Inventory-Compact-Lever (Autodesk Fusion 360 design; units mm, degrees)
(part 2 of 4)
sketch "Spring-side loaded retained M4 nut" plane through (0, 0, 37.9) normal (0, 0, 1) x axis (1, 0, 0)
  line L1 (14.1362, -51.3) -> (16.2724, -55)
  line L2 (9.8638, -51.3) -> (14.1362, -51.3)
  line L3 (7.7276, -55) -> (9.8638, -51.3)
  line L4 (9.8638, -58.7) -> (7.7276, -55)
  line L5 (14.1362, -58.7) -> (9.8638, -58.7)
  line L6 (16.2724, -55) -> (14.1362, -58.7)
extrude "Extrude7" cut sketch "Spring-side loaded retained M4 nut" along normal blind 3.5
work_plane "WorkPlane8" AlongDistance 37.9 ExtraOffset 0
sketch "Spring cup guide bolts" plane through (0, 0, 37.9) normal (0, 0, 1) x axis (1, 0, 0)
  circle C1 centre (5, -55) radius 1.7
extrude "Extrude8" cut sketch "Spring cup guide bolts" along normal blind 14.2
work_plane "WorkPlane9" AlongDistance 37.9 ExtraOffset 0
sketch "Spring cup guide bolts (1)" plane through (0, 0, 37.9) normal (0, 0, 1) x axis (1, 0, 0)
  circle C1 centre (19, -55) radius 1.7
extrude "Extrude9" cut sketch "Spring cup guide bolts (1)" along normal blind 14.2
work_plane "WorkPlane11" AlongDistance -18 ExtraOffset 0
sketch "Dedicated thick stop lug" plane through (-18, 0, 0) normal (1, 0, 0) x axis (0, 0, -1)
  line L1 (-72, 5) -> (-72, -5)
  line L2 (-95, 5) -> (-72, 5)
  line L3 (-95, -5) -> (-95, 5)
  line L4 (-72, -5) -> (-95, -5)
extrude "Extrude11" add sketch "Dedicated thick stop lug" along normal blind 11.5
work_plane "WorkPlane12" AlongDistance -18 ExtraOffset 0
sketch "Rounded stop contact" plane through (-18, 0, 0) normal (1, 0, 0) x axis (0, 0, -1)
  circle C1 centre (-95, 0) radius 5
extrude "Extrude12" add sketch "Rounded stop contact" along normal blind 11.5
work_plane "WorkPlane10" AlongDistance -36 ExtraOffset 0
sketch "Broad stop support ear" plane through (-36, 0, 0) normal (1, 0, 0) x axis (0, 0, -1)
  line L1 (-60, -20) -> (-60, -44)
  line L2 (-90, -20) -> (-60, -20)
  line L3 (-90, -44) -> (-90, -20)
  line L4 (-60, -44) -> (-90, -44)
extrude "Extrude10" add sketch "Broad stop support ear" along normal blind 12
work_plane "WorkPlane11" AlongDistance -24 ExtraOffset 0
sketch "Integrated steel-core end stop" plane through (-24, 0, 0) normal (1, 0, 0) x axis (0, 0, -1)
  circle C1 centre (-79.6754, -33.9652) radius 6
extrude "Extrude11" add sketch "Integrated steel-core end stop" along normal blind 15
work_plane "WorkPlane12" AlongDistance -36.1 ExtraOffset 0
sketch "M5 stop reinforcement bolt" plane through (-36.1, 0, 0) normal (1, 0, 0) x axis (0, 0, -1)
  circle C1 centre (-79.6754, -33.9652) radius 2.7
extrude "Extrude12" cut sketch "M5 stop reinforcement bolt" along normal blind 27.2
work_plane "WorkPlane13" AlongDistance -15.4 ExtraOffset 0
sketch "M5 captive stop nut" plane through (-15.4, 0, 0) normal (1, 0, 0) x axis (0, 0, -1)
  line L1 (-83.8754, -31.5403) -> (-79.6754, -29.1154)
  line L2 (-83.8754, -36.39) -> (-83.8754, -31.5403)
  line L3 (-79.6754, -38.8149) -> (-83.8754, -36.39)
  line L4 (-75.4754, -36.39) -> (-79.6754, -38.8149)
  line L5 (-75.4754, -31.5403) -> (-75.4754, -36.39)
  line L6 (-79.6754, -29.1154) -> (-75.4754, -31.5403)
extrude "Extrude13" cut sketch "M5 captive stop nut" along normal blind 6.5
work_plane "WorkPlane14" AlongDistance -36 ExtraOffset 0
sketch "Broad stop support ear (1)" plane through (-36, 0, 0) normal (1, 0, 0) x axis (0, 0, -1)
  line L1 (-60, 44) -> (-60, 20)
  line L2 (-90, 44) -> (-60, 44)
  line L3 (-90, 20) -> (-90, 44)
  line L4 (-60, 20) -> (-90, 20)
extrude "Extrude14" add sketch "Broad stop support ear (1)" along normal blind 12
work_plane "WorkPlane15" AlongDistance -24 ExtraOffset 0
sketch "Integrated steel-core end stop (1)" plane through (-24, 0, 0) normal (1, 0, 0) x axis (0, 0, -1)
  circle C1 centre (-79.6754, 33.9652) radius 6
extrude "Extrude15" add sketch "Integrated steel-core end stop (1)" along normal blind 15
work_plane "WorkPlane16" AlongDistance -36.1 ExtraOffset 0
sketch "M5 stop reinforcement bolt (1)" plane through (-36.1, 0, 0) normal (1, 0, 0) x axis (0, 0, -1)
  circle C1 centre (-79.6754, 33.9652) radius 2.7
extrude "Extrude16" cut sketch "M5 stop reinforcement bolt (1)" along normal blind 27.2
work_plane "WorkPlane17" AlongDistance -15.4 ExtraOffset 0
sketch "M5 captive stop nut (1)" plane through (-15.4, 0, 0) normal (1, 0, 0) x axis (0, 0, -1)
  line L1 (-83.8754, 36.39) -> (-79.6754, 38.8149)
  line L2 (-83.8754, 31.5403) -> (-83.8754, 36.39)
  line L3 (-79.6754, 29.1154) -> (-83.8754, 31.5403)
  line L4 (-75.4754, 31.5403) -> (-79.6754, 29.1154)
  line L5 (-75.4754, 36.39) -> (-75.4754, 31.5403)
  line L6 (-79.6754, 38.8149) -> (-75.4754, 36.39)
extrude "Extrude17" cut sketch "M5 captive stop nut (1)" along normal blind 6.5
work_plane "WorkPlane13" AlongDistance -24 ExtraOffset 0
sketch "Restore shaft socket through stop-lug root" plane through (-24, 0, 0) normal (1, 0, 0) x axis (0, 0, -1)
  line L1 (-69.6247, 6.65) -> (-60.3753, 6.65)
  arc A1 centre (-65, 0) radius 8.1 clockwise from (-60.3753, 6.65) to (-69.6247, 6.65)
extrude "Extrude13" cut sketch "Restore shaft socket through stop-lug root" along normal blind 48
work_plane "WorkPlane10" AlongDistance -24.1 ExtraOffset 0
sketch "Cam sweep clearance through crossblock" plane through (-24.1, 0, 0) normal (1, 0, 0) x axis (0, 0, -1)
  circle C1 centre (-65, 0) radius 51
extrude "Extrude10" cut sketch "Cam sweep clearance through crossblock" along normal blind 48.2
work_plane "WorkPlane10" AlongDistance 36 ExtraOffset 0
sketch "Rigid sensor carriage support" plane through (36, 0, 0) normal (1, 0, 0) x axis (0, 0, -1)
  line L1 (-49, -18) -> (-49, -28)
  line L2 (-81, -18) -> (-49, -18)
  line L3 (-81, -28) -> (-81, -18)
  line L4 (-49, -28) -> (-81, -28)
extrude "Extrude10" add sketch "Rigid sensor carriage support" along normal blind 44
work_plane "WorkPlane11" AlongDistance -28.1 ExtraOffset 0
sketch "M3 sensor carriage heat set" plane through (0, -28.1, 0) normal (0, 1, 0) x axis (1, 0, 0)
  circle C1 centre (74, -65) radius 2
extrude "Extrude11" cut sketch "M3 sensor carriage heat set" along normal blind 6.8
work_plane "WorkPlane12" AlongDistance 36 ExtraOffset 0
sketch "Rigid sensor carriage support (1)" plane through (36, 0, 0) normal (1, 0, 0) x axis (0, 0, -1)
  line L1 (-49, 28) -> (-49, 18)
  line L2 (-81, 28) -> (-49, 28)
  line L3 (-81, 18) -> (-81, 28)
  line L4 (-49, 18) -> (-81, 18)
extrude "Extrude12" add sketch "Rigid sensor carriage support (1)" along normal blind 44
work_plane "WorkPlane13" AlongDistance 21.3 ExtraOffset 0
sketch "M3 sensor carriage heat set (1)" plane through (0, 21.3, 0) normal (0, 1, 0) x axis (1, 0, 0)
  circle C1 centre (74, -65) radius 2
extrude "Extrude13" cut sketch "M3 sensor carriage heat set (1)" along normal blind 6.8
work_plane "WorkPlane1" AlongDistance -24 ExtraOffset 0
sketch "Controlled follower end float" plane through (-24, 0, 0) normal (1, 0, 0) x axis (0, 0, -1)
  circle C1 centre (-12, -35) radius 6
extrude "Extrude1" new body sketch "Controlled follower end float" along normal blind 27.8 bodies "P21 Follower left axial spacer"
work_plane "WorkPlane2" AlongDistance -24.1 ExtraOffset 0
sketch "Pivot sleeve running clearance" plane through (-24.1, 0, 0) normal (1, 0, 0) x axis (0, 0, -1)
  circle C1 centre (-12, -35) radius 4.2
extrude "Extrude2" cut sketch "Pivot sleeve running clearance" along normal blind 28
work_plane "WorkPlane1" AlongDistance 20.2 ExtraOffset 0
sketch "Controlled follower end float" plane through (20.2, 0, 0) normal (1, 0, 0) x axis (0, 0, -1)
  circle C1 centre (-12, -35) radius 6
extrude "Extrude1" new body sketch "Controlled follower end float" along normal blind 3.8 bodies "P22 Follower right axial spacer"
work_plane "WorkPlane2" AlongDistance 20.1 ExtraOffset 0
sketch "Pivot sleeve running clearance" plane through (20.1, 0, 0) normal (1, 0, 0) x axis (0, 0, -1)
  circle C1 centre (-12, -35) radius 4.2
extrude "Extrude2" cut sketch "Pivot sleeve running clearance" along normal blind 4
work_plane "WorkPlane1" AlongDistance 3.1 ExtraOffset 0
sketch "Roller axle M3 nut" plane through (3.1, 0, 0) normal (1, 0, 0) x axis (0, 0, -1)
  line L1 (-14.75, 1.5877) -> (-12, 3.1754)
  line L2 (-14.75, -1.5877) -> (-14.75, 1.5877)
  line L3 (-12, -3.1754) -> (-14.75, -1.5877)
  line L4 (-9.25, -1.5877) -> (-12, -3.1754)
  line L5 (-9.25, 1.5877) -> (-9.25, -1.5877)
  line L6 (-12, 3.1754) -> (-9.25, 1.5877)
extrude "Extrude1" new body sketch "Roller axle M3 nut" along normal blind 2.4 bodies "HARDWARE Roller axle M3 nut"
work_plane "WorkPlane2" AlongDistance 3 ExtraOffset 0
sketch "Thread envelope" plane through (3, 0, 0) normal (1, 0, 0) x axis (0, 0, -1)
  circle C1 centre (-12, 0) radius 1.5
extrude "Extrude2" cut sketch "Thread envelope" along normal blind 2.6
work_plane "WorkPlane14" AlongDistance 23.9 ExtraOffset 0
sketch "Cam lateral service opening" plane through (23.9, 0, 0) normal (1, 0, 0) x axis (0, 0, -1)
  line L1 (-42.2047, 46.7373) -> (-43.8497, 47.5044)
  line L2 (-40.5875, 45.9133) -> (-42.2047, 46.7373)
  line L3 (-39, 45.0333) -> (-40.5875, 45.9133)
  line L4 (-37.4442, 44.0985) -> (-39, 45.0333)
  line L5 (-35.922, 43.11) -> (-37.4442, 44.0985)
  line L6 (-34.4352, 42.0689) -> (-35.922, 43.11)
  line L7 (-32.9856, 40.9766) -> (-34.4352, 42.0689)
  line L8 (-31.575, 39.8343) -> (-32.9856, 40.9766)
  line L9 (-30.2052, 38.6435) -> (-31.575, 39.8343)
  line L10 (-28.8778, 37.4057) -> (-30.2052, 38.6435)
  line L11 (-27.5943, 36.1222) -> (-28.8778, 37.4057)
  line L12 (-26.3565, 34.7948) -> (-27.5943, 36.1222)
  line L13 (-25.1657, 33.425) -> (-26.3565, 34.7948)
  line L14 (-24.0234, 32.0144) -> (-25.1657, 33.425)
  line L15 (-22.9311, 30.5648) -> (-24.0234, 32.0144)
  line L16 (-21.89, 29.078) -> (-22.9311, 30.5648)
  line L17 (-20.9015, 27.5558) -> (-21.89, 29.078)
  line L18 (-19.9667, 26) -> (-20.9015, 27.5558)
  line L19 (-19.0867, 24.4125) -> (-19.9667, 26)
  line L20 (-18.2627, 22.7953) -> (-19.0867, 24.4125)
  line L21 (-17.4956, 21.1503) -> (-18.2627, 22.7953)
  line L22 (-16.7864, 19.4795) -> (-17.4956, 21.1503)
  line L23 (-16.136, 17.785) -> (-16.7864, 19.4795)
  line L24 (-15.5451, 16.0689) -> (-16.136, 17.785)
  line L25 (-15.0144, 14.3331) -> (-15.5451, 16.0689)
  line L26 (-14.5446, 12.5799) -> (-15.0144, 14.3331)
  line L27 (-14.1363, 10.8114) -> (-14.5446, 12.5799)
  line L28 (-13.79, 9.0297) -> (-14.1363, 10.8114)
  line L29 (-13.5061, 7.237) -> (-13.79, 9.0297)
  line L30 (-13.2849, 5.4355) -> (-13.5061, 7.237)
  line L31 (-13.1267, 3.6273) -> (-13.2849, 5.4355)
  line L32 (-13.0317, 1.8148) -> (-13.1267, 3.6273)
  line L33 (-13, 0) -> (-13.0317, 1.8148)
  line L34 (-13.0317, -1.8148) -> (-13, 0)
  line L35 (-13.1267, -3.6273) -> (-13.0317, -1.8148)
  line L36 (-13.2849, -5.4355) -> (-13.1267, -3.6273)
  line L37 (-13.5061, -7.237) -> (-13.2849, -5.4355)
  line L38 (-13.79, -9.0297) -> (-13.5061, -7.237)
  line L39 (-14.1363, -10.8114) -> (-13.79, -9.0297)
  line L40 (-14.5446, -12.5799) -> (-14.1363, -10.8114)
  line L41 (-15.0144, -14.3331) -> (-14.5446, -12.5799)
  line L42 (-15.5451, -16.0689) -> (-15.0144, -14.3331)
  line L43 (-16.136, -17.785) -> (-15.5451, -16.0689)
  line L44 (-16.7864, -19.4795) -> (-16.136, -17.785)
  line L45 (-17.4956, -21.1503) -> (-16.7864, -19.4795)
  line L46 (-18.2627, -22.7953) -> (-17.4956, -21.1503)
  line L47 (-19.0867, -24.4125) -> (-18.2627, -22.7953)
  line L48 (-19.9667, -26) -> (-19.0867, -24.4125)
  line L49 (-20.9015, -27.5558) -> (-19.9667, -26)
  line L50 (-21.89, -29.078) -> (-20.9015, -27.5558)
  line L51 (-22.9311, -30.5648) -> (-21.89, -29.078)
  line L52 (-24.0234, -32.0144) -> (-22.9311, -30.5648)
  line L53 (-25.1657, -33.425) -> (-24.0234, -32.0144)
  line L54 (-26.3565, -34.7948) -> (-25.1657, -33.425)
  line L55 (-27.5943, -36.1222) -> (-26.3565, -34.7948)
  line L56 (-28.8778, -37.4057) -> (-27.5943, -36.1222)
  line L57 (-30.2052, -38.6435) -> (-28.8778, -37.4057)
  line L58 (-31.575, -39.8343) -> (-30.2052, -38.6435)
  line L59 (-32.9856, -40.9766) -> (-31.575, -39.8343)
  line L60 (-34.4352, -42.0689) -> (-32.9856, -40.9766)
  line L61 (-35.922, -43.11) -> (-34.4352, -42.0689)
  line L62 (-37.4442, -44.0985) -> (-35.922, -43.11)
  line L63 (-39, -45.0333) -> (-37.4442, -44.0985)
  line L64 (-40.5875, -45.9133) -> (-39, -45.0333)
  line L65 (-42.2047, -46.7373) -> (-40.5875, -45.9133)
  line L66 (-43.8497, -47.5044) -> (-42.2047, -46.7373)
  line L67 (-54.4248, -23.7522) -> (-43.8497, -47.5044)
  line L68 (-53.6024, -23.3686) -> (-54.4248, -23.7522)
  line L69 (-52.7937, -22.9566) -> (-53.6024, -23.3686)
  line L70 (-52, -22.5167) -> (-52.7937, -22.9566)
  line L71 (-51.2221, -22.0493) -> (-52, -22.5167)
  line L72 (-50.461, -21.555) -> (-51.2221, -22.0493)
  line L73 (-49.7176, -21.0344) -> (-50.461, -21.555)
  line L74 (-48.9928, -20.4883) -> (-49.7176, -21.0344)
  line L75 (-48.2875, -19.9172) -> (-48.9928, -20.4883)
  line L76 (-47.6026, -19.3218) -> (-48.2875, -19.9172)
  line L77 (-46.9389, -18.7028) -> (-47.6026, -19.3218)
  line L78 (-46.2972, -18.0611) -> (-46.9389, -18.7028)
  line L79 (-45.6782, -17.3974) -> (-46.2972, -18.0611)
  line L80 (-45.0828, -16.7125) -> (-45.6782, -17.3974)
  line L81 (-44.5117, -16.0072) -> (-45.0828, -16.7125)
  line L82 (-43.9656, -15.2824) -> (-44.5117, -16.0072)
  line L83 (-43.445, -14.539) -> (-43.9656, -15.2824)
  line L84 (-42.9507, -13.7779) -> (-43.445, -14.539)
  line L85 (-42.4833, -13) -> (-42.9507, -13.7779)
  line L86 (-42.0434, -12.2063) -> (-42.4833, -13)
  line L87 (-41.6314, -11.3976) -> (-42.0434, -12.2063)
  line L88 (-41.2478, -10.5752) -> (-41.6314, -11.3976)
  line L89 (-40.8932, -9.7398) -> (-41.2478, -10.5752)
  line L90 (-40.568, -8.8925) -> (-40.8932, -9.7398)
  line L91 (-40.2725, -8.0344) -> (-40.568, -8.8925)
  line L92 (-40.0072, -7.1666) -> (-40.2725, -8.0344)
  line L93 (-39.7723, -6.29) -> (-40.0072, -7.1666)
  line L94 (-39.5682, -5.4057) -> (-39.7723, -6.29)
  line L95 (-39.395, -4.5149) -> (-39.5682, -5.4057)
  line L96 (-39.253, -3.6185) -> (-39.395, -4.5149)
  line L97 (-39.1424, -2.7177) -> (-39.253, -3.6185)
  line L98 (-39.0633, -1.8137) -> (-39.1424, -2.7177)
  line L99 (-39.0158, -0.9074) -> (-39.0633, -1.8137)
  line L100 (-39, 0) -> (-39.0158, -0.9074)
  line L101 (-39.0158, 0.9074) -> (-39, 0)
  line L102 (-39.0633, 1.8137) -> (-39.0158, 0.9074)
  line L103 (-39.1424, 2.7177) -> (-39.0633, 1.8137)
  line L104 (-39.253, 3.6185) -> (-39.1424, 2.7177)
  line L105 (-39.395, 4.5149) -> (-39.253, 3.6185)
  line L106 (-39.5682, 5.4057) -> (-39.395, 4.5149)
  line L107 (-39.7723, 6.29) -> (-39.5682, 5.4057)
  line L108 (-40.0072, 7.1666) -> (-39.7723, 6.29)
  line L109 (-40.2725, 8.0344) -> (-40.0072, 7.1666)
  line L110 (-40.568, 8.8925) -> (-40.2725, 8.0344)
  line L111 (-40.8932, 9.7398) -> (-40.568, 8.8925)
  line L112 (-41.2478, 10.5752) -> (-40.8932, 9.7398)
  line L113 (-41.6314, 11.3976) -> (-41.2478, 10.5752)
  line L114 (-42.0434, 12.2063) -> (-41.6314, 11.3976)
  line L115 (-42.4833, 13) -> (-42.0434, 12.2063)
  line L116 (-42.9507, 13.7779) -> (-42.4833, 13)
  line L117 (-43.445, 14.539) -> (-42.9507, 13.7779)
  line L118 (-43.9656, 15.2824) -> (-43.445, 14.539)
  line L119 (-44.5117, 16.0072) -> (-43.9656, 15.2824)
  line L120 (-45.0828, 16.7125) -> (-44.5117, 16.0072)
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extrude "Extrude14" cut sketch "Cam lateral service opening" along normal blind 12.2
work_plane "WorkPlane15" AlongDistance 36 ExtraOffset 0
sketch "Clear service path beneath sensor rails" plane through (36, 0, 0) normal (1, 0, 0) x axis (0, 0, -1)
  line L1 (-48.9, -18) -> (-48.9, -28)
  line L2 (-56, -18) -> (-48.9, -18)
  line L3 (-56, -28) -> (-56, -18)
  line L4 (-48.9, -28) -> (-56, -28)
extrude "Extrude15" cut sketch "Clear service path beneath sensor rails" along normal blind 44.1
work_plane "WorkPlane16" AlongDistance 36 ExtraOffset 0
sketch "Clear service path beneath sensor rails (1)" plane through (36, 0, 0) normal (1, 0, 0) x axis (0, 0, -1)
  line L1 (-48.9, 28) -> (-48.9, 18)
  line L2 (-56, 28) -> (-48.9, 28)
  line L3 (-56, 18) -> (-56, 28)
  line L4 (-48.9, 18) -> (-56, 18)
extrude "Extrude16" cut sketch "Clear service path beneath sensor rails (1)" along normal blind 44.1
work_plane "WorkPlane11" AlongDistance -24 ExtraOffset 0
sketch "Raise mount clear of rail bolt axes" plane through (-24, 0, 0) normal (1, 0, 0) x axis (0, 0, -1)
  line L1 (-52, -44) -> (-52, -66)
  line L2 (-57, -44) -> (-52, -44)
  line L3 (-57, -66) -> (-57, -44)
  line L4 (-52, -66) -> (-57, -66)
extrude "Extrude11" add sketch "Raise mount clear of rail bolt axes" along normal blind 48
work_plane "WorkPlane12" AlongDistance -24 ExtraOffset 0
sketch "Close old block mounting hole" plane through (-24, 0, 0) normal (1, 0, 0) x axis (0, 0, -1)
  circle C1 centre (-44, -59) radius 2.01
extrude "Extrude12" add sketch "Close old block mounting hole" along normal blind 8.7
work_plane "WorkPlane13" AlongDistance -24.1 ExtraOffset 0
sketch "Raised M3 block insert" plane through (-24.1, 0, 0) normal (1, 0, 0) x axis (0, 0, -1)
  circle C1 centre (-52, -59) radius 2
extrude "Extrude13" cut sketch "Raised M3 block insert" along normal blind 8.9
work_plane "WorkPlane14" AlongDistance 15.3 ExtraOffset 0
sketch "Close old block mounting hole (1)" plane through (15.3, 0, 0) normal (1, 0, 0) x axis (0, 0, -1)
  circle C1 centre (-44, -59) radius 2.01
extrude "Extrude14" add sketch "Close old block mounting hole (1)" along normal blind 8.7
work_plane "WorkPlane15" AlongDistance 15.2 ExtraOffset 0
sketch "Raised M3 block insert (1)" plane through (15.2, 0, 0) normal (1, 0, 0) x axis (0, 0, -1)
  circle C1 centre (-52, -59) radius 2
extrude "Extrude15" cut sketch "Raised M3 block insert (1)" along normal blind 8.9
work_plane "WorkPlane18" AlongDistance -36 ExtraOffset 0
sketch "Close old plate mounting hole" plane through (-36, 0, 0) normal (1, 0, 0) x axis (0, 0, -1)
  circle C1 centre (-44, -59) radius 1.71
extrude "Extrude18" add sketch "Close old plate mounting hole" along normal blind 12
work_plane "WorkPlane19" AlongDistance -36.1 ExtraOffset 0
sketch "Raised M3 block fastener" plane through (-36.1, 0, 0) normal (1, 0, 0) x axis (0, 0, -1)
  circle C1 centre (-52, -59) radius 1.7
extrude "Extrude19" cut sketch "Raised M3 block fastener" along normal blind 12.2
work_plane "WorkPlane17" AlongDistance 24 ExtraOffset 0
sketch "Close old plate mounting hole" plane through (24, 0, 0) normal (1, 0, 0) x axis (0, 0, -1)
  circle C1 centre (-44, -59) radius 1.71
extrude "Extrude17" add sketch "Close old plate mounting hole" along normal blind 12
work_plane "WorkPlane18" AlongDistance 23.9 ExtraOffset 0
sketch "Raised M3 block fastener" plane through (23.9, 0, 0) normal (1, 0, 0) x axis (0, 0, -1)
  circle C1 centre (-52, -59) radius 1.7
extrude "Extrude18" cut sketch "Raised M3 block fastener" along normal blind 12.2
work_plane "WorkPlane16" AlongDistance -24 ExtraOffset 0
sketch "Close old block mounting hole (2)" plane through (-24, 0, 0) normal (1, 0, 0) x axis (0, 0, -1)
  circle C1 centre (-44, -51) radius 2.01
extrude "Extrude16" add sketch "Close old block mounting hole (2)" along normal blind 8.7
work_plane "WorkPlane17" AlongDistance -24.1 ExtraOffset 0
sketch "Raised M3 block insert (2)" plane through (-24.1, 0, 0) normal (1, 0, 0) x axis (0, 0, -1)
  circle C1 centre (-52, -51) radius 2
extrude "Extrude17" cut sketch "Raised M3 block insert (2)" along normal blind 8.9
work_plane "WorkPlane18" AlongDistance 15.3 ExtraOffset 0
sketch "Close old block mounting hole (3)" plane through (15.3, 0, 0) normal (1, 0, 0) x axis (0, 0, -1)
  circle C1 centre (-44, -51) radius 2.01
extrude "Extrude18" add sketch "Close old block mounting hole (3)" along normal blind 8.7
work_plane "WorkPlane19" AlongDistance 15.2 ExtraOffset 0
sketch "Raised M3 block insert (3)" plane through (15.2, 0, 0) normal (1, 0, 0) x axis (0, 0, -1)
  circle C1 centre (-52, -51) radius 2
extrude "Extrude19" cut sketch "Raised M3 block insert (3)" along normal blind 8.9
work_plane "WorkPlane20" AlongDistance -36 ExtraOffset 0
sketch "Close old plate mounting hole (1)" plane through (-36, 0, 0) normal (1, 0, 0) x axis (0, 0, -1)
  circle C1 centre (-44, -51) radius 1.71
extrude "Extrude20" add sketch "Close old plate mounting hole (1)" along normal blind 12
work_plane "WorkPlane21" AlongDistance -36.1 ExtraOffset 0
sketch "Raised M3 block fastener (1)" plane through (-36.1, 0, 0) normal (1, 0, 0) x axis (0, 0, -1)
  circle C1 centre (-52, -51) radius 1.7
extrude "Extrude21" cut sketch "Raised M3 block fastener (1)" along normal blind 12.2
work_plane "WorkPlane19" AlongDistance 24 ExtraOffset 0
sketch "Close old plate mounting hole (1)" plane through (24, 0, 0) normal (1, 0, 0) x axis (0, 0, -1)
  circle C1 centre (-44, -51) radius 1.71
extrude "Extrude19" add sketch "Close old plate mounting hole (1)" along normal blind 12
work_plane "WorkPlane20" AlongDistance 23.9 ExtraOffset 0
sketch "Raised M3 block fastener (1)" plane through (23.9, 0, 0) normal (1, 0, 0) x axis (0, 0, -1)
  circle C1 centre (-52, -51) radius 1.7
extrude "Extrude20" cut sketch "Raised M3 block fastener (1)" along normal blind 12.2
work_plane "WorkPlane20" AlongDistance 51.9 ExtraOffset 0
sketch "Continue adjuster bore" plane through (0, 0, 51.9) normal (0, 0, 1) x axis (1, 0, 0)
  circle C1 centre (12, -55) radius 2.2
extrude "Extrude20" cut sketch "Continue adjuster bore" along normal blind 5.2
work_plane "WorkPlane21" AlongDistance 51.9 ExtraOffset 0
sketch "Continue guide bore" plane through (0, 0, 51.9) normal (0, 0, 1) x axis (1, 0, 0)
  circle C1 centre (5, -55) radius 1.7
extrude "Extrude21" cut sketch "Continue guide bore" along normal blind 5.2
work_plane "WorkPlane22" AlongDistance 51.9 ExtraOffset 0
sketch "Continue guide bore (1)" plane through (0, 0, 51.9) normal (0, 0, 1) x axis (1, 0, 0)
  circle C1 centre (19, -55) radius 1.7
extrude "Extrude22" cut sketch "Continue guide bore (1)" along normal blind 5.2
work_plane "WorkPlane23" AlongDistance -24.1 ExtraOffset 0
sketch "Preserve cam sweep clearance" plane through (-24.1, 0, 0) normal (1, 0, 0) x axis (0, 0, -1)
  circle C1 centre (-65, 0) radius 51
extrude "Extrude23" cut sketch "Preserve cam sweep clearance" along normal blind 48.2
work_plane "WorkPlane8" AlongDistance 37.25 ExtraOffset 0
sketch "Flat shoulder aligns with shaft print bed" plane through (37.25, 0, 0) normal (1, 0, 0) x axis (0, 0, -1)
  line L1 (-54, 11) -> (-54, 6.5)
  line L2 (-76, 11) -> (-54, 11)
  line L3 (-76, 6.5) -> (-76, 11)
  line L4 (-54, 6.5) -> (-76, 6.5)
extrude "Extrude8" cut sketch "Flat shoulder aligns with shaft print bed" along normal blind 3.2
work_plane "WorkPlane1" AlongDistance -23.85 ExtraOffset 0
sketch "Controlled rotor axial clearance" plane through (-23.85, 0, 0) normal (1, 0, 0) x axis (0, 0, -1)
  circle C1 centre (-65, 0) radius 10
extrude "Extrude1" new body sketch "Controlled rotor axial clearance" along normal blind 16.85 bodies "P23 Left rotor thrust spacer"
work_plane "WorkPlane2" AlongDistance -23.95 ExtraOffset 0
sketch "Free spacer bore" plane through (-23.95, 0, 0) normal (1, 0, 0) x axis (0, 0, -1)
  circle C1 centre (-65, 0) radius 8.2
extrude "Extrude2" cut sketch "Free spacer bore" along normal blind 17.05
work_plane "WorkPlane1" AlongDistance 7 ExtraOffset 0
sketch "Controlled rotor axial clearance" plane through (7, 0, 0) normal (1, 0, 0) x axis (0, 0, -1)
  circle C1 centre (-65, 0) radius 10
extrude "Extrude1" new body sketch "Controlled rotor axial clearance" along normal blind 16.85 bodies "P24 Right rotor thrust spacer"
work_plane "WorkPlane2" AlongDistance 6.9 ExtraOffset 0
sketch "Free spacer bore" plane through (6.9, 0, 0) normal (1, 0, 0) x axis (0, 0, -1)
  circle C1 centre (-65, 0) radius 8.2
extrude "Extrude2" cut sketch "Free spacer bore" along normal blind 17.05
work_plane "WorkPlane22" AlongDistance -76 ExtraOffset 0
sketch "Restore rail bolt clearance after hole filling" plane through (0, -76, 0) normal (0, 1, 0) x axis (1, 0, 0)
  circle C1 centre (-30, -45) radius 2.7
extrude "Extrude22" cut sketch "Restore rail bolt clearance after hole filling" along normal blind 22
work_plane "WorkPlane23" AlongDistance 54 ExtraOffset 0
sketch "Restore rail bolt clearance after hole filling (1)" plane through (0, 54, 0) normal (0, 1, 0) x axis (1, 0, 0)
  circle C1 centre (-30, -45) radius 2.7
work_plane "WorkPlane24" AlongDistance -55 ExtraOffset 0
sketch "Restore rail head access after hole filling" plane through (0, -55, 0) normal (0, 1, 0) x axis (1, 0, 0)
  circle C1 centre (-30, -45) radius 5.3
extrude "Extrude24" cut sketch "Restore rail head access after hole filling" along normal blind 12
work_plane "WorkPlane25" AlongDistance 43 ExtraOffset 0
sketch "Restore rail head access after hole filling (1)" plane through (0, 43, 0) normal (0, 1, 0) x axis (1, 0, 0)
  circle C1 centre (-30, -45) radius 5.3
work_plane "WorkPlane21" AlongDistance -76 ExtraOffset 0
sketch "Restore rail bolt clearance after hole filling" plane through (0, -76, 0) normal (0, 1, 0) x axis (1, 0, 0)
  circle C1 centre (30, -45) radius 2.7
extrude "Extrude21" cut sketch "Restore rail bolt clearance after hole filling" along normal blind 22
work_plane "WorkPlane22" AlongDistance 54 ExtraOffset 0
sketch "Restore rail bolt clearance after hole filling (1)" plane through (0, 54, 0) normal (0, 1, 0) x axis (1, 0, 0)
  circle C1 centre (30, -45) radius 2.7
work_plane "WorkPlane23" AlongDistance -55 ExtraOffset 0
sketch "Restore rail head access after hole filling" plane through (0, -55, 0) normal (0, 1, 0) x axis (1, 0, 0)
  circle C1 centre (30, -45) radius 5.3
extrude "Extrude23" cut sketch "Restore rail head access after hole filling" along normal blind 12
work_plane "WorkPlane24" AlongDistance 43 ExtraOffset 0
sketch "Restore rail head access after hole filling (1)" plane through (0, 43, 0) normal (0, 1, 0) x axis (1, 0, 0)
  circle C1 centre (30, -45) radius 5.3
work_plane "WorkPlane14" AlongDistance -18.1 ExtraOffset 0
sketch "Stop lug clearance for concentric thrust spacer" plane through (-18.1, 0, 0) normal (1, 0, 0) x axis (0, 0, -1)
  circle C1 centre (-65, 0) radius 10.2
extrude "Extrude14" cut sketch "Stop lug clearance for concentric thrust spacer" along normal blind 11
work_plane "WorkPlane15" AlongDistance -18.1 ExtraOffset 0
sketch "Complete stop lug relief to rotor face" plane through (-18.1, 0, 0) normal (1, 0, 0) x axis (0, 0, -1)
  circle C1 centre (-65, 0) radius 10.2
extrude "Extrude15" cut sketch "Complete stop lug relief to rotor face" along normal blind 11.1
ground "Pin2"
ground "Pin3"
ground "Pin4"
ground "Pin5"
ground "Pin6"
ground "Pin11"
ground "Pin12"
ground "Pin48"
ground "Pin49"
work_plane "WorkPlane24" AlongDistance -24 ExtraOffset 0
sketch "Extra roof over relocated heat-set inserts" plane through (-24, 0, 0) normal (1, 0, 0) x axis (0, 0, -1)
  line L1 (-57, -44) -> (-57, -66)
  line L2 (-59, -44) -> (-57, -44)
  line L3 (-59, -66) -> (-59, -44)
  line L4 (-57, -66) -> (-59, -66)
extrude "Extrude24" add sketch "Extra roof over relocated heat-set inserts" along normal blind 48
work_plane "WorkPlane25" AlongDistance -24 ExtraOffset 0
sketch "Fill former insert location" plane through (-24, 0, 0) normal (1, 0, 0) x axis (0, 0, -1)
  circle C1 centre (-52, -59) radius 2.01
extrude "Extrude25" add sketch "Fill former insert location" along normal blind 8.7
work_plane "WorkPlane26" AlongDistance 15.3 ExtraOffset 0
sketch "Fill former insert location (1)" plane through (15.3, 0, 0) normal (1, 0, 0) x axis (0, 0, -1)
  circle C1 centre (-52, -59) radius 2.01
extrude "Extrude26" add sketch "Fill former insert location (1)" along normal blind 8.7
work_plane "WorkPlane26" AlongDistance -36 ExtraOffset 0
sketch "Fill former plate mounting hole" plane through (-36, 0, 0) normal (1, 0, 0) x axis (0, 0, -1)
  circle C1 centre (-52, -59) radius 1.71
extrude "Extrude26" add sketch "Fill former plate mounting hole" along normal blind 12
work_plane "WorkPlane25" AlongDistance 24 ExtraOffset 0
sketch "Fill former plate mounting hole" plane through (24, 0, 0) normal (1, 0, 0) x axis (0, 0, -1)
  circle C1 centre (-52, -59) radius 1.71
extrude "Extrude25" add sketch "Fill former plate mounting hole" along normal blind 12
work_plane "WorkPlane27" AlongDistance -24 ExtraOffset 0
sketch "Fill former insert location (2)" plane through (-24, 0, 0) normal (1, 0, 0) x axis (0, 0, -1)
  circle C1 centre (-52, -51) radius 2.01
extrude "Extrude27" add sketch "Fill former insert location (2)" along normal blind 8.7
work_plane "WorkPlane28" AlongDistance 15.3 ExtraOffset 0
sketch "Fill former insert location (3)" plane through (15.3, 0, 0) normal (1, 0, 0) x axis (0, 0, -1)
  circle C1 centre (-52, -51) radius 2.01
extrude "Extrude28" add sketch "Fill former insert location (3)" along normal blind 8.7
work_plane "WorkPlane27" AlongDistance -36 ExtraOffset 0
sketch "Fill former plate mounting hole (1)" plane through (-36, 0, 0) normal (1, 0, 0) x axis (0, 0, -1)
  circle C1 centre (-52, -51) radius 1.71
extrude "Extrude27" add sketch "Fill former plate mounting hole (1)" along normal blind 12
work_plane "WorkPlane26" AlongDistance 24 ExtraOffset 0
sketch "Fill former plate mounting hole (1)" plane through (24, 0, 0) normal (1, 0, 0) x axis (0, 0, -1)
  circle C1 centre (-52, -51) radius 1.71
extrude "Extrude26" add sketch "Fill former plate mounting hole (1)" along normal blind 12
work_plane "WorkPlane29" AlongDistance -24.1 ExtraOffset 0
sketch "Relocated insert with cam-side retaining wall" plane through (-24.1, 0, 0) normal (1, 0, 0) x axis (0, 0, -1)
  circle C1 centre (-53.5, -62) radius 2
extrude "Extrude29" cut sketch "Relocated insert with cam-side retaining wall" along normal blind 8.9
work_plane "WorkPlane30" AlongDistance 15.3 ExtraOffset 0
sketch "Relocated insert with cam-side retaining wall (1)" plane through (15.3, 0, 0) normal (1, 0, 0) x axis (0, 0, -1)
  circle C1 centre (-53.5, -62) radius 2
extrude "Extrude30" cut sketch "Relocated insert with cam-side retaining wall (1)" along normal blind 8.9
work_plane "WorkPlane28" AlongDistance -36.1 ExtraOffset 0
sketch "Relocated mount above rail counterbore" plane through (-36.1, 0, 0) normal (1, 0, 0) x axis (0, 0, -1)
  circle C1 centre (-53.5, -62) radius 1.7
extrude "Extrude28" cut sketch "Relocated mount above rail counterbore" along normal blind 12.2
work_plane "WorkPlane27" AlongDistance 23.9 ExtraOffset 0
sketch "Relocated mount above rail counterbore" plane through (23.9, 0, 0) normal (1, 0, 0) x axis (0, 0, -1)
  circle C1 centre (-53.5, -62) radius 1.7
extrude "Extrude27" cut sketch "Relocated mount above rail counterbore" along normal blind 12.2
work_plane "WorkPlane31" AlongDistance -24.1 ExtraOffset 0
sketch "Relocated insert with cam-side retaining wall (2)" plane through (-24.1, 0, 0) normal (1, 0, 0) x axis (0, 0, -1)
  circle C1 centre (-53.5, -54) radius 2
extrude "Extrude31" cut sketch "Relocated insert with cam-side retaining wall (2)" along normal blind 8.9
work_plane "WorkPlane32" AlongDistance 15.3 ExtraOffset 0
sketch "Relocated insert with cam-side retaining wall (3)" plane through (15.3, 0, 0) normal (1, 0, 0) x axis (0, 0, -1)
  circle C1 centre (-53.5, -54) radius 2
extrude "Extrude32" cut sketch "Relocated insert with cam-side retaining wall (3)" along normal blind 8.9
work_plane "WorkPlane29" AlongDistance -36.1 ExtraOffset 0
sketch "Relocated mount above rail counterbore (1)" plane through (-36.1, 0, 0) normal (1, 0, 0) x axis (0, 0, -1)
  circle C1 centre (-53.5, -54) radius 1.7
extrude "Extrude29" cut sketch "Relocated mount above rail counterbore (1)" along normal blind 12.2
work_plane "WorkPlane28" AlongDistance 23.9 ExtraOffset 0
sketch "Relocated mount above rail counterbore (1)" plane through (23.9, 0, 0) normal (1, 0, 0) x axis (0, 0, -1)
  circle C1 centre (-53.5, -54) radius 1.7
extrude "Extrude28" cut sketch "Relocated mount above rail counterbore (1)" along normal blind 12.2
work_plane "WorkPlane33" AlongDistance 51.9 ExtraOffset 0
sketch "Continue adjuster bore through roof" plane through (0, 0, 51.9) normal (0, 0, 1) x axis (1, 0, 0)
  circle C1 centre (12, -55) radius 2.2
extrude "Extrude33" cut sketch "Continue adjuster bore through roof" along normal blind 7.2
work_plane "WorkPlane34" AlongDistance 51.9 ExtraOffset 0
sketch "Continue guide bore through roof" plane through (0, 0, 51.9) normal (0, 0, 1) x axis (1, 0, 0)
  circle C1 centre (5, -55) radius 1.7
extrude "Extrude34" cut sketch "Continue guide bore through roof" along normal blind 7.2
work_plane "WorkPlane35" AlongDistance 51.9 ExtraOffset 0
sketch "Continue guide bore through roof (1)" plane through (0, 0, 51.9) normal (0, 0, 1) x axis (1, 0, 0)
  circle C1 centre (19, -55) radius 1.7
extrude "Extrude35" cut sketch "Continue guide bore through roof (1)" along normal blind 7.2
work_plane "WorkPlane36" AlongDistance -24.1 ExtraOffset 0
sketch "Restore cam envelope after pocket repair" plane through (-24.1, 0, 0) normal (1, 0, 0) x axis (0, 0, -1)
  circle C1 centre (-65, 0) radius 51
extrude "Extrude36" cut sketch "Restore cam envelope after pocket repair" along normal blind 48.2
work_plane "WorkPlane30" AlongDistance -76 ExtraOffset 0
sketch "Preserve rail shank passage" plane through (0, -76, 0) normal (0, 1, 0) x axis (1, 0, 0)
  circle C1 centre (-30, -45) radius 2.7
work_plane "WorkPlane31" AlongDistance 54 ExtraOffset 0
sketch "Preserve rail shank passage (1)" plane through (0, 54, 0) normal (0, 1, 0) x axis (1, 0, 0)
  circle C1 centre (-30, -45) radius 2.7
work_plane "WorkPlane32" AlongDistance -55 ExtraOffset 0
sketch "Preserve rail head passage" plane through (0, -55, 0) normal (0, 1, 0) x axis (1, 0, 0)
  circle C1 centre (-30, -45) radius 5.3
extrude "Extrude32" cut sketch "Preserve rail head passage" along normal blind 12
work_plane "WorkPlane33" AlongDistance 43 ExtraOffset 0
sketch "Preserve rail head passage (1)" plane through (0, 43, 0) normal (0, 1, 0) x axis (1, 0, 0)
  circle C1 centre (-30, -45) radius 5.3
work_plane "WorkPlane29" AlongDistance -76 ExtraOffset 0
sketch "Preserve rail shank passage" plane through (0, -76, 0) normal (0, 1, 0) x axis (1, 0, 0)
  circle C1 centre (30, -45) radius 2.7
work_plane "WorkPlane30" AlongDistance 54 ExtraOffset 0
sketch "Preserve rail shank passage (1)" plane through (0, 54, 0) normal (0, 1, 0) x axis (1, 0, 0)
  circle C1 centre (30, -45) radius 2.7
work_plane "WorkPlane31" AlongDistance -55 ExtraOffset 0
sketch "Preserve rail head passage" plane through (0, -55, 0) normal (0, 1, 0) x axis (1, 0, 0)
  circle C1 centre (30, -45) radius 5.3
extrude "Extrude31" cut sketch "Preserve rail head passage" along normal blind 12
work_plane "WorkPlane32" AlongDistance 43 ExtraOffset 0
sketch "Preserve rail head passage (1)" plane through (0, 43, 0) normal (0, 1, 0) x axis (1, 0, 0)
  circle C1 centre (30, -45) radius 5.3
work_plane "WorkPlane16" AlongDistance -5 ExtraOffset 0
sketch "Flat washer seat for sensor-drive shaft clamp" plane through (-5, 0, 0) normal (1, 0, 0) x axis (0, 0, -1)
  line L1 (-60, 22) -> (-60, 20)
  line L2 (-70, 22) -> (-60, 22)
  line L3 (-70, 20) -> (-70, 22)
  line L4 (-60, 20) -> (-70, 20)
extrude "Extrude16" add sketch "Flat washer seat for sensor-drive shaft clamp" along normal blind 10
work_plane "WorkPlane17" AlongDistance 6.4 ExtraOffset 0
sketch "Radial screw onto printed shaft D flat" plane through (0, 6.4, 0) normal (0, 1, 0) x axis (1, 0, 0)
  circle C1 centre (0, -65) radius 1.7
extrude "Extrude17" cut sketch "Radial screw onto printed shaft D flat" along normal blind 15.7
work_plane "WorkPlane18" AlongDistance 15.2 ExtraOffset 0
sketch "M3 heatset pocket for rotor clamp" plane through (0, 15.2, 0) normal (0, 1, 0) x axis (1, 0, 0)
  circle C1 centre (0, -65) radius 2
extrude "Extrude18" cut sketch "M3 heatset pocket for rotor clamp" along normal blind 6.9
work_plane "WorkPlane37" AlongDistance -24 ExtraOffset 0
sketch "Extend reaction block into free rail bay" plane through (-24, 0, 0) normal (1, 0, 0) x axis (0, 0, -1)
  line L1 (-38, -66) -> (-38, -74)
  line L2 (-59, -66) -> (-38, -66)
  line L3 (-59, -74) -> (-59, -66)
  line L4 (-38, -74) -> (-59, -74)
extrude "Extrude37" add sketch "Extend reaction block into free rail bay" along normal blind 48
work_plane "WorkPlane38" AlongDistance -24 ExtraOffset 0
sketch "Close mounting bore that crossed cup guide" plane through (-24, 0, 0) normal (1, 0, 0) x axis (0, 0, -1)
  circle C1 centre (-53.5, -54) radius 2.01
extrude "Extrude38" add sketch "Close mounting bore that crossed cup guide" along normal blind 8.7
work_plane "WorkPlane39" AlongDistance -24.1 ExtraOffset 0
sketch "Outer mounting row clear of guide" plane through (-24.1, 0, 0) normal (1, 0, 0) x axis (0, 0, -1)
  circle C1 centre (-53.5, -70) radius 2
extrude "Extrude39" cut sketch "Outer mounting row clear of guide" along normal blind 8.9
work_plane "WorkPlane40" AlongDistance 15.3 ExtraOffset 0
sketch "Close mounting bore that crossed cup guide (1)" plane through (15.3, 0, 0) normal (1, 0, 0) x axis (0, 0, -1)
  circle C1 centre (-53.5, -54) radius 2.01
extrude "Extrude40" add sketch "Close mounting bore that crossed cup guide (1)" along normal blind 8.7
work_plane "WorkPlane41" AlongDistance 15.2 ExtraOffset 0
sketch "Outer mounting row clear of guide (1)" plane through (15.2, 0, 0) normal (1, 0, 0) x axis (0, 0, -1)
  circle C1 centre (-53.5, -70) radius 2
extrude "Extrude41" cut sketch "Outer mounting row clear of guide (1)" along normal blind 8.9
work_plane "WorkPlane34" AlongDistance -36 ExtraOffset 0
sketch "Close former inner mounting hole" plane through (-36, 0, 0) normal (1, 0, 0) x axis (0, 0, -1)
  circle C1 centre (-53.5, -54) radius 1.71
extrude "Extrude34" add sketch "Close former inner mounting hole" along normal blind 12
work_plane "WorkPlane35" AlongDistance -36.1 ExtraOffset 0
sketch "Matched outer mounting row" plane through (-36.1, 0, 0) normal (1, 0, 0) x axis (0, 0, -1)
  circle C1 centre (-53.5, -70) radius 1.7
extrude "Extrude35" cut sketch "Matched outer mounting row" along normal blind 12.2
work_plane "WorkPlane33" AlongDistance 24 ExtraOffset 0
sketch "Close former inner mounting hole" plane through (24, 0, 0) normal (1, 0, 0) x axis (0, 0, -1)
  circle C1 centre (-53.5, -54) radius 1.71
extrude "Extrude33" add sketch "Close former inner mounting hole" along normal blind 12
work_plane "WorkPlane34" AlongDistance 23.9 ExtraOffset 0
sketch "Matched outer mounting row" plane through (23.9, 0, 0) normal (1, 0, 0) x axis (0, 0, -1)
  circle C1 centre (-53.5, -70) radius 1.7
extrude "Extrude34" cut sketch "Matched outer mounting row" along normal blind 12.2
work_plane "WorkPlane42" AlongDistance 37.9 ExtraOffset 0
sketch "Restore separate cup guide bore" plane through (0, 0, 37.9) normal (0, 0, 1) x axis (1, 0, 0)
  circle C1 centre (5, -55) radius 1.7
work_plane "WorkPlane43" AlongDistance 37.9 ExtraOffset 0
sketch "Restore separate cup guide bore (1)" plane through (0, 0, 37.9) normal (0, 0, 1) x axis (1, 0, 0)
  circle C1 centre (19, -55) radius 1.7
extrude "Extrude43" cut sketch "Restore separate cup guide bore (1)" along normal blind 21.2
work_plane "WorkPlane44" AlongDistance -24.1 ExtraOffset 0
sketch "Preserve cam envelope" plane through (-24.1, 0, 0) normal (1, 0, 0) x axis (0, 0, -1)
  circle C1 centre (-65, 0) radius 51
work_plane "WorkPlane36" AlongDistance -55 ExtraOffset 0
sketch "Close inaccessible rail head pocket" plane through (0, -55, 0) normal (0, 1, 0) x axis (1, 0, 0)
  circle C1 centre (-30, -45) radius 5.31
extrude "Extrude36" add sketch "Close inaccessible rail head pocket" along normal blind 12
work_plane "WorkPlane37" AlongDistance 43 ExtraOffset 0
sketch "Close inaccessible rail head pocket (1)" plane through (0, 43, 0) normal (0, 1, 0) x axis (1, 0, 0)
  circle C1 centre (-30, -45) radius 5.31
extrude "Extrude37" add sketch "Close inaccessible rail head pocket (1)" along normal blind 12
work_plane "WorkPlane38" AlongDistance -75 ExtraOffset 0
sketch "Close obsolete side rail bore" plane through (0, -75, 0) normal (0, 1, 0) x axis (1, 0, 0)
  circle C1 centre (-30, -45) radius 2.71
extrude "Extrude38" add sketch "Close obsolete side rail bore" along normal blind 20
work_plane "WorkPlane39" AlongDistance 55 ExtraOffset 0
sketch "Close obsolete side rail bore (1)" plane through (0, 55, 0) normal (0, 1, 0) x axis (1, 0, 0)
  circle C1 centre (-30, -45) radius 2.71
extrude "Extrude39" add sketch "Close obsolete side rail bore (1)" along normal blind 20
work_plane "WorkPlane40" AlongDistance -36 ExtraOffset 0
sketch "Top-access 2020 mounting flange" plane through (-36, 0, 0) normal (1, 0, 0) x axis (0, 0, -1)
  line L1 (-55, -70) -> (-55, -95)
  line L2 (-63, -70) -> (-55, -70)
  line L3 (-63, -95) -> (-63, -70)
  line L4 (-55, -95) -> (-63, -95)
extrude "Extrude40" add sketch "Top-access 2020 mounting flange" along normal blind 12
work_plane "WorkPlane41" AlongDistance -36 ExtraOffset 0
sketch "Mount root triangular reinforcement" plane through (-36, 0, 0) normal (1, 0, 0) x axis (0, 0, -1)
  line L1 (-56, -63) -> (-56, -70)
  line L2 (-63, -70) -> (-56, -63)
  line L3 (-56, -70) -> (-63, -70)
extrude "Extrude41" add sketch "Mount root triangular reinforcement" along normal blind 12
work_plane "WorkPlane42" AlongDistance 54.9 ExtraOffset 0
sketch "Vertical M5 rail mounting bore" plane through (0, 0, 54.9) normal (0, 0, 1) x axis (1, 0, 0)
  circle C1 centre (-30, -85) radius 2.7
extrude "Extrude42" cut sketch "Vertical M5 rail mounting bore" along normal blind 8.2
work_plane "WorkPlane43" AlongDistance -36 ExtraOffset 0
sketch "Top-access 2020 mounting flange (1)" plane through (-36, 0, 0) normal (1, 0, 0) x axis (0, 0, -1)
  line L1 (-55, 95) -> (-55, 70)
  line L2 (-63, 95) -> (-55, 95)
  line L3 (-63, 70) -> (-63, 95)
  line L4 (-55, 70) -> (-63, 70)
extrude "Extrude43" add sketch "Top-access 2020 mounting flange (1)" along normal blind 12
work_plane "WorkPlane44" AlongDistance -36 ExtraOffset 0
sketch "Mount root triangular reinforcement (1)" plane through (-36, 0, 0) normal (1, 0, 0) x axis (0, 0, -1)
  line L1 (-56, 70) -> (-56, 63)
  line L2 (-63, 70) -> (-56, 70)
  line L3 (-56, 63) -> (-63, 70)
extrude "Extrude44" add sketch "Mount root triangular reinforcement (1)" along normal blind 12
work_plane "WorkPlane45" AlongDistance 54.9 ExtraOffset 0
sketch "Vertical M5 rail mounting bore (1)" plane through (0, 0, 54.9) normal (0, 0, 1) x axis (1, 0, 0)
  circle C1 centre (-30, 85) radius 2.7
extrude "Extrude45" cut sketch "Vertical M5 rail mounting bore (1)" along normal blind 8.2
work_plane "WorkPlane46" AlongDistance -36 ExtraOffset 0
sketch "Close old M5 pivot clearance" plane through (-36, 0, 0) normal (1, 0, 0) x axis (0, 0, -1)
  circle C1 centre (-12, -35) radius 2.71
extrude "Extrude46" add sketch "Close old M5 pivot clearance" along normal blind 12
work_plane "WorkPlane47" AlongDistance -36.1 ExtraOffset 0
sketch "M3 follower pivot clearance" plane through (-36.1, 0, 0) normal (1, 0, 0) x axis (0, 0, -1)
  circle C1 centre (-12, -35) radius 1.7
extrude "Extrude47" cut sketch "M3 follower pivot clearance" along normal blind 12.2
work_plane "WorkPlane35" AlongDistance -55 ExtraOffset 0
sketch "Close inaccessible rail head pocket" plane through (0, -55, 0) normal (0, 1, 0) x axis (1, 0, 0)
  circle C1 centre (30, -45) radius 5.31
extrude "Extrude35" add sketch "Close inaccessible rail head pocket" along normal blind 12
work_plane "WorkPlane36" AlongDistance 43 ExtraOffset 0
sketch "Close inaccessible rail head pocket (1)" plane through (0, 43, 0) normal (0, 1, 0) x axis (1, 0, 0)
  circle C1 centre (30, -45) radius 5.31
extrude "Extrude36" add sketch "Close inaccessible rail head pocket (1)" along normal blind 12
work_plane "WorkPlane37" AlongDistance -75 ExtraOffset 0
sketch "Close obsolete side rail bore" plane through (0, -75, 0) normal (0, 1, 0) x axis (1, 0, 0)
  circle C1 centre (30, -45) radius 2.71
extrude "Extrude37" add sketch "Close obsolete side rail bore" along normal blind 20
work_plane "WorkPlane38" AlongDistance 55 ExtraOffset 0
sketch "Close obsolete side rail bore (1)" plane through (0, 55, 0) normal (0, 1, 0) x axis (1, 0, 0)
  circle C1 centre (30, -45) radius 2.71
extrude "Extrude38" add sketch "Close obsolete side rail bore (1)" along normal blind 20
work_plane "WorkPlane39" AlongDistance 24 ExtraOffset 0
sketch "Top-access 2020 mounting flange" plane through (24, 0, 0) normal (1, 0, 0) x axis (0, 0, -1)
  line L1 (-55, -70) -> (-55, -95)
  line L2 (-63, -70) -> (-55, -70)
  line L3 (-63, -95) -> (-63, -70)
  line L4 (-55, -95) -> (-63, -95)
extrude "Extrude39" add sketch "Top-access 2020 mounting flange" along normal blind 12
work_plane "WorkPlane40" AlongDistance 24 ExtraOffset 0
sketch "Mount root triangular reinforcement" plane through (24, 0, 0) normal (1, 0, 0) x axis (0, 0, -1)
  line L1 (-56, -63) -> (-56, -70)
  line L2 (-63, -70) -> (-56, -63)
  line L3 (-56, -70) -> (-63, -70)
extrude "Extrude40" add sketch "Mount root triangular reinforcement" along normal blind 12
work_plane "WorkPlane41" AlongDistance 54.9 ExtraOffset 0
sketch "Vertical M5 rail mounting bore" plane through (0, 0, 54.9) normal (0, 0, 1) x axis (1, 0, 0)
  circle C1 centre (30, -85) radius 2.7
extrude "Extrude41" cut sketch "Vertical M5 rail mounting bore" along normal blind 8.2
work_plane "WorkPlane42" AlongDistance 24 ExtraOffset 0
sketch "Top-access 2020 mounting flange (1)" plane through (24, 0, 0) normal (1, 0, 0) x axis (0, 0, -1)
  line L1 (-55, 95) -> (-55, 70)
  line L2 (-63, 95) -> (-55, 95)
  line L3 (-63, 70) -> (-63, 95)
  line L4 (-55, 70) -> (-63, 70)
extrude "Extrude42" add sketch "Top-access 2020 mounting flange (1)" along normal blind 12
work_plane "WorkPlane43" AlongDistance 24 ExtraOffset 0
sketch "Mount root triangular reinforcement (1)" plane through (24, 0, 0) normal (1, 0, 0) x axis (0, 0, -1)
  line L1 (-56, 70) -> (-56, 63)
  line L2 (-63, 70) -> (-56, 70)
  line L3 (-56, 63) -> (-63, 70)
extrude "Extrude43" add sketch "Mount root triangular reinforcement (1)" along normal blind 12
work_plane "WorkPlane44" AlongDistance 54.9 ExtraOffset 0
sketch "Vertical M5 rail mounting bore (1)" plane through (0, 0, 54.9) normal (0, 0, 1) x axis (1, 0, 0)
  circle C1 centre (30, 85) radius 2.7
extrude "Extrude44" cut sketch "Vertical M5 rail mounting bore (1)" along normal blind 8.2
work_plane "WorkPlane45" AlongDistance 24 ExtraOffset 0
sketch "Close old M5 pivot clearance" plane through (24, 0, 0) normal (1, 0, 0) x axis (0, 0, -1)
  circle C1 centre (-12, -35) radius 2.71
extrude "Extrude45" add sketch "Close old M5 pivot clearance" along normal blind 12
work_plane "WorkPlane46" AlongDistance 23.9 ExtraOffset 0
sketch "M3 follower pivot clearance" plane through (23.9, 0, 0) normal (1, 0, 0) x axis (0, 0, -1)
  circle C1 centre (-12, -35) radius 1.7
extrude "Extrude46" cut sketch "M3 follower pivot clearance" along normal blind 12.2
work_plane "WorkPlane47" AlongDistance 23.9 ExtraOffset 0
